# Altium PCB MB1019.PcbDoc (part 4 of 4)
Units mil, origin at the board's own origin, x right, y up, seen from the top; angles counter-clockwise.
Board outline 4655 x 6805 mil, 4 copper layers (TopLayer, VCC, GND, BottomLayer), stack 26.137 mil thick; 557 components, 425 nets, 1918 pads, 817 vias.
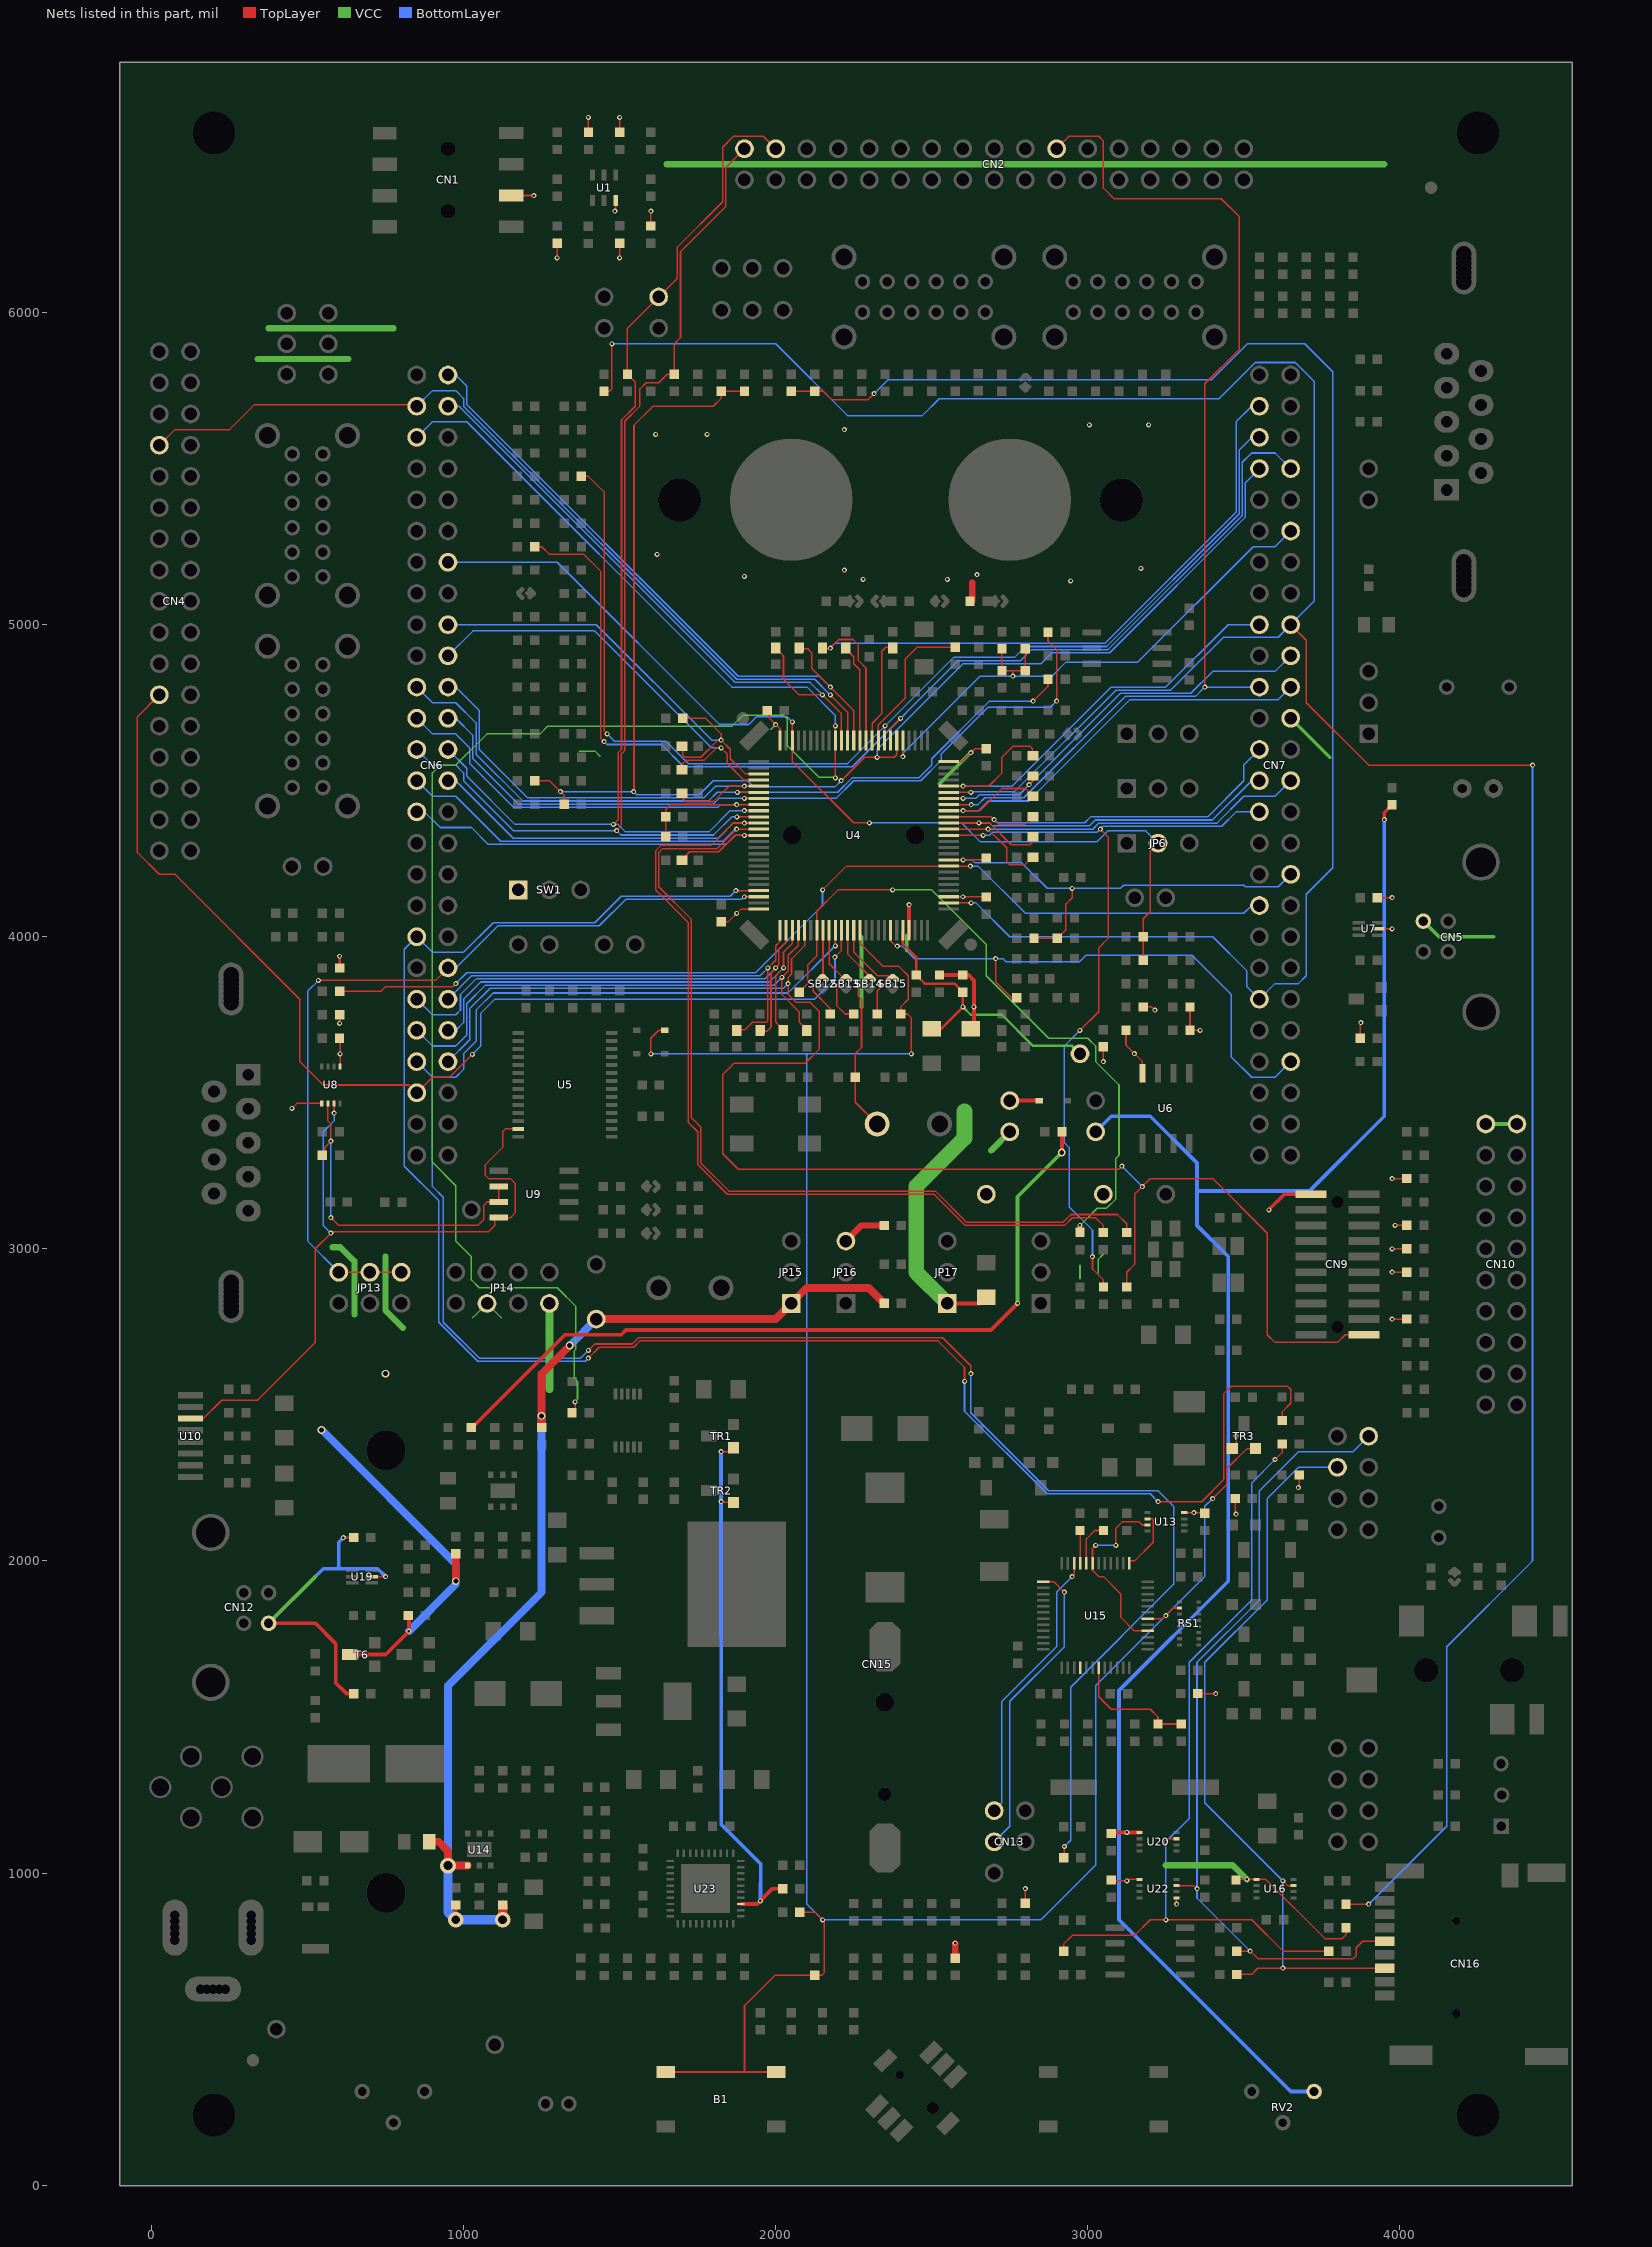
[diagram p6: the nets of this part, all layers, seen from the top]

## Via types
v1: diameter 16, hole 8, TopLayer to BottomLayer, tented both sides, 770 vias
v2: diameter 16, hole 8, TopLayer to BottomLayer, 26 vias
v3: diameter 25, hole 16, TopLayer to BottomLayer, tented both sides, 17 vias
v4: diameter 50, hole 28, TopLayer to BottomLayer, tented both sides, 4 vias

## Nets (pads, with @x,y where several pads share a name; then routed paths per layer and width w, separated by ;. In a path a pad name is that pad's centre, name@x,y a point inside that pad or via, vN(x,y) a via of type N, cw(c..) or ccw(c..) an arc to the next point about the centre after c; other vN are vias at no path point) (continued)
PC4: CN7.35 R177.2 U4.33 | length 3216.3
  TopLayer w5: R177.2@602.5,3825 735,3825 750,3840 965,3840 v1(975,3850) ; v1(2150,4150) 2226.58,4226.58 v1(2623.42,4226.58)
  BottomLayer w5: v1(975,3850) 1010,3885 1935,3885 2150,4100 v1(2150,4150) ; v1(2623.42,4226.58) 2648.42,4226.58 2800,4075 3500,4075 3525,4100 CN7.35@3550,4100
PC5: C33.2 CN7.34 R117.2 R118.2 U4.34 | length 1484.5
  TopLayer w5: U4.34@2554.13,4246.26 C33.2@2673.74,4246.26 ; R117.2@2827.5,3995 2902.5,3995 2930,4022.5 2930,4105 2950,4125 v1(2950,4155)
  BottomLayer w5: v1(2600.32,4246.26) 2628.74,4246.26 2638.42,4236.58 2788.42,4236.58 2870,4155 3105,4155 3115,4165 3500,4165 3505,4160 3610,4160 CN7.34@3650,4200
PC6: CN6.2 R47.2 R48.2 U4.63 | length 2056.3
  TopLayer w5: R47.2@2075,4922.5 2102.5,4922.5 2115,4910 2115,4860 2250,4725 U4.63@2250,4629.13
  BottomLayer w5: CN6.2@950,5800 975,5800 1010,5765 1010,5705 1880,4835 2140,4835 v1(2175,4800)
PC7: CN4.7 CN6.3 U4.64 | length 2796.8
  TopLayer w5: CN4.7@25,5575 75,5625 250,5625 330,5705 CN6.3@835,5705 ; v1(2175.14,4774.86) 2230.31,4719.69 U4.64@2230.31,4629.13
  BottomLayer w5: CN6.3@850,5700 900,5750 975,5750 1000,5725 1000,5700 1875,4825 2125,4825 v1(2175.14,4774.86)
PC8: CN6.4 R49.2 R50.2 U4.65 | length 2012.4
  TopLayer w5: R49.2@2000,4927.5 2000,4925 2025,4900 2025,4825 2075,4775 2149.73,4775 v1(2149.87,4775.13) ; v1@2150,4775 2210.63,4714.37 U4.65@2210.63,4629.13
  BottomLayer w5: CN6.4@950,5700 985,5700 1870,4815 2110,4815 v1(2149.87,4775.13)
PC9: CN6.5 R247.2 U4.66 | length 5848
  TopLayer w5: R247.2@1355,2475 1357.5,2477.5 v1(1357.5,2510) ; v1@2190.94,4510.94 v1(2190.94,4675.31)
  VCC w5: v1(1357.5,2510) 1365,2517.5 1365,2575 1355,2585 1355,2673.91 1360,2678.91 1360,2815 1300,2875 1050,2875 1025,2900 1025,2975 975,3025 975,3202.31 900,3277.31 900,4525 925,4550 975,4550 1075,4650 1245,4650 1270,4675 1860,4675 1895,4710 2025,4710 2036.85,4698.15 2036.85,4613.15 2139.06,4510.94 2190.94,4510.94 v1@2190,4510
  BottomLayer w5: CN6.5@850,5600 900,5650 1010,5650 1860,4800 2100,4800 2190.94,4709.06 v1(2190.94,4675.31)
  other v1: 1357.5,2510 2190.94,4509
PC10: CN6.18 R51.2 R52.2 R129.2 U4.78 | length 1550.6
  TopLayer w5: R51.2@1702.5,4610 1702.5,4582.5 1710,4575 1760,4575 1815,4630 v1(1825,4630) ; R129.2@1702.5,4700 1775,4700 1825,4650 v1(1825,4630) ; U4.78@1945.87,4521.85 1903.15,4521.85 1854.38,4570.62 1854.38,4600.62 v1(1825,4630)
  BottomLayer w5: CN6.18@950,5000 1425,5000 1795,4630 v1(1825,4630)
PC11: CN6.20 R53.2 R54.2 U4.79 | length 1407.7
  TopLayer w5: R53.2@1702.5,4535 1702.5,4555 1712.5,4565 1770,4565 1810,4605 v1(1825,4605) 1844.38,4585.62 1844.38,4555.62 1897.84,4502.17 U4.79@1945.87,4502.17
  BottomLayer w5: CN6.20@950,4900 1030,4980 1420,4980 1795,4605 v1(1825,4605)
PC12: CN6.22 R55.2 R56.2 U4.80 | length 1470.7
  TopLayer w5: R55.2@1702.5,4460 1702.5,4442.5 1711.57,4433.42 1800.94,4433.42 1850,4482.48 U4.80@1945.87,4482.48
  BottomLayer w5: CN6.22@950,4800 975,4800 1050,4725 1050,4600 1205,4445 1770,4445 1807.48,4482.48 v1(1900,4482.48)
PC13: R187.1 R308.2 U4.7 | length 2170.2
  TopLayer w5: R187.1@2075,3822.5 R187.1@2075,3825 ; R187.1@2075.16,3822.62 2103.26,3850.72 2103.26,3910 2131.89,3938.63 2131.89,4081.89 2200,4150 v1(2375,4150) ; R308.2@2975,3052.5 v1(2975,3075)
  VCC w5: v1(2375,4150) 2500,4150 2675,3975 2675,3875 2875,3675 3000,3675 3025,3650 3025,3600 3100,3525 3100,3300 3090,3290 3090,3160 3060,3130 3030,3130 v1(2975,3075)
PC14: R196.2 SB12.1 U4.8 | length 304.2
  TopLayer w5: U4.8@2151.57,4020.87 2151.57,3874.43 2120,3842.85 2120,3825 2175,3770 R196.2@2175,3752.5
PC15: R197.2 SB13.1 U4.9 | length 335.3
  TopLayer w5: U4.9@2171.26,4020.87 2171.26,3913.74 SB13.1@2217,3868 2195,3846 2195,3780 2222.5,3752.5 R197.2@2250,3752.5
PD0: CN6.21 R124.1 U4.81 | length 2487.4
  TopLayer w5: v1(1877.2,4462.8) U4.81@1945.87,4462.8 ; v1(2825,4755) 2872.5,4802.5 R124.1@2872.5,4825
  BottomLayer w5: CN6.21@850,4800 900,4750 975,4750 1040,4685 1040,4585 1190,4435 1785,4435 1812.8,4462.8 2198.65,4462.8 2245.86,4510 2460,4510 2500,4550 2500,4570 2685,4755 v1(2825,4755)
PD1: CN6.24 R105.2 U4.82 | length 2533.5
  TopLayer w5: v1(1900,4443.11) U4.82@1945.87,4443.11 ; R105.2@2872.5,4975 2872.5,4947.5 2900,4920 v1(2900,4755)
  BottomLayer w5: CN6.24@950,4700 975,4700 1030,4645 1030,4570 1175,4425 1800,4425 1818.11,4443.11 2193.11,4443.11 2250,4500 2465,4500 2530,4565 2530,4585 2680,4735 2880,4735 v1(2900,4755)
PD2: CN6.23 R153.1 R165.1 U4.83 | length 1573.3
  TopLayer w5: R165.1@1647.5,4315 1647.5,4407.5 1663.43,4423.42 U4.83@1945.87,4423.42
  BottomLayer w5: CN6.23@850,4700 900,4650 975,4650 1020,4605 1020,4555 1160,4415 1815,4415 1823.43,4423.42 v1(1875,4423.42)
PD3: C10.2 CN2.31 CN6.26 JP2.1 U4.84 | length 3684.7
  TopLayer w5: v1(1480,4360) 1495,4375 1495,4590 1506,4601 1506,5656 1550,5700 1550,5777.5 C10.2@1525,5802.5 1525,5950 1685,6110 1685,6210 1830,6355 1830,6530 1865,6565 1960,6565 CN2.31@2000,6525 ; v1(1900,4403.74) U4.84@1945.87,4403.74
  BottomLayer w5: CN6.26@950,4600 1010,4540 1010,4515 1165,4360 1495,4360 1519.06,4335.94 1785.94,4335.94 1853.74,4403.74 v1(1900,4403.74)
PD4: C12.2 CN2.33 CN6.25 U4.85 | length 3639.5
  TopLayer w5: v1(1490,4340) 1505,4355 1505,4585.86 1516,4596.86 1516,5651.86 1565,5700.86 1565,5755 1585,5775 1625,5775 1652.5,5802.5 C12.2@1675,5802.5 1675,5900 1695,5920 1695,6195 1840,6340 1840,6465 CN2.33@1900,6525 ; v1(1875.94,4384.06) U4.85@1945.87,4384.06
  BottomLayer w5: CN6.25@850,4600 900,4550 975,4550 1000,4525 1000,4500 1160,4340 v1(1490,4340) 1504.06,4325.94 1800.94,4325.94 1859.06,4384.06 v1(1875.94,4384.06)
PD5: CN6.28 R22.1 U4.86 | length 3899.1
  TopLayer w5: U4.86@1945.87,4364.37 1864.37,4364.37 1792.5,4292.5 1632.5,4292.5 1615,4275 1615,4150.71 1720,4045.71 1720,3405 1750,3375 1750,3270 1845,3175 2507.57,3175 2607.57,3075 2925,3075 2950,3100 3025,3100 3050,3075 R22.1@3050,3052.5
  BottomLayer w5: CN6.28@950,4500 975,4500 1159.06,4315.94 1815.94,4315.94 1864.37,4364.37 v1(1900,4364.37)
PD6: CN6.27 R12.1 U4.87 | length 4017.8
  TopLayer w5: U4.87@1945.87,4344.68 v1(1874.69,4344.68) 1812.5,4282.5 1637.5,4282.5 1625,4270 1625,4160 1730,4055 1730,3420 1760,3390 1760,3275 1850,3185 2511.72,3185 2611.72,3085 2920.86,3085 2945.86,3110 3095,3110 3125,3080 R12.1@3125,3052.5
  BottomLayer w5: CN6.27@850,4500 900,4450 975,4450 1119.06,4305.94 1830.94,4305.94 1869.69,4344.68 v1(1874.69,4344.68)
PD7: CN6.29 R57.2 R58.2 U4.88 | length 1379.6
  TopLayer w5: R57.2@1702.5,4250 1725,4272.5 1817.5,4272.5 1870,4325 U4.88@1945.87,4325
  BottomLayer w5: CN6.29@850,4400 875,4400 925,4350 1025,4350 1079.06,4295.94 1840.94,4295.94 1870,4325 v1(1900,4325)
PD8: C22.2 C23.2 CN7.12 R119.1 R123.1 U4.55 | length 1835.3
  TopLayer w5: v1(2407.48,4577.52) U4.55@2407.48,4629.13 ; R123.1@2722.5,4925 2725,4922.5 C22.2@2725,4852.5 C23.2@2800,4852.5 R119.1@2800,4922.5 ; v1(2760,4835) 2760,4852.5
  BottomLayer w5: v1(2407.48,4577.52) 2407.48,4587.48 2655,4835 2885,4835 2930,4880 3160,4880 3530,5250 3600,5250 CN7.12@3650,5300
PD9: C7.2 C26.2 CN7.7 R80.1 R146.1 U4.56 | length 4615.1
  TopLayer w5: R146.1@1227.5,4497.5 1227.5,4500 1275,4500 1322.5,4452.5 C26.2@1322.5,4425 ; v1@1546,4466 1546,5639.43 1606.57,5700 1800,5700 1825,5725 C7.2@1825,5747.5 R80.1@1900,5747.5 ; v1(2210,4500) 2285,4575 2380,4575 2387.79,4582.79 U4.56@2387.79,4629.13
  BottomLayer w5: v1(1310,4465) v1(1545,4465) 1555,4455 1755,4455 1800,4500 1910,4500 1930,4480 2190,4480 v1(2210,4500) ; v1(2325,4575) 2325,4600 2600,4875 2850,4875 2885,4910 3070,4910 3505,5345 3505,5455 CN7.7@3550,5500
PD10: CN7.8 R100.1 U4.57 | length 3648.6
  TopLayer w5: R100.1@1227.5,5250 1250,5250 1275,5225 1385,5225 1440,5170 1440,4635 v1(1450,4625) ; U4.57@2368.11,4629.13 2368.11,4668.11 v1(2400,4700)
  BottomLayer w5: v1(1450,4625) 1459.11,4615.89 1634.11,4615.89 1705,4545 2245,4545 2585,4885 2785,4885 2820,4920 3065,4920 3495,5350 3495,5520 3525,5550 3600,5550 CN7.8@3650,5500
PD11: CN7.5 R92.1 U4.58 | length 3601.6
  TopLayer w5: R92.1@1377.5,5475 1400,5475 1450,5425 1450,4660 v1(1460,4650) ; U4.58@2348.42,4629.13 2348.42,4673.42 v1(2350.29,4675.29)
  BottomLayer w5: v1(1460,4650) 1484.11,4625.89 1649.11,4625.89 1720,4555 2230,4555 2570,4895 2765,4895 2800,4930 3060,4930 3485,5355 3485,5560 3525,5600 CN7.5@3550,5600
PD12: R39.2 R40.2 U4.59 | length 472.1
  TopLayer w5: U4.59@2328.74,4629.13 2328.74,4678.74 2415,4765 2415,4890 2452.5,4927.5 R39.2@2575,4927.5
PD13: R41.2 R42.2 U4.60 | length 338.9
  TopLayer w5: U4.60@2309.05,4629.13 2309.05,4684.05 2340,4715 2340,4915 2352.5,4927.5 R41.2@2375,4927.5
PD14: CN7.3 R45.2 R46.2 U4.61 | length 2316.4
  TopLayer w5: R45.2@2150,4922.5 2172.5,4922.5 2202.38,4952.38 2247.62,4952.38 2265,4935 2265,4885 2289.37,4860.63 U4.61@2289.37,4629.13
  BottomLayer w5: v1(2175,4925) 2190,4940 3055,4940 3475,5360 3475,5650 3525,5700 CN7.3@3550,5700
PD15: R43.2 R44.2 U4.62 | length 311.9
  TopLayer w5: R43.2@2225,4922.5 2250,4897.5 2250,4875 2269.68,4855.32 U4.62@2269.68,4629.13
PE0: CN6.37 R250.1 U4.97 | length 6029.6
  TopLayer w5: v1(1400,2650) 1435,2685 1545,2685 1565,2705 2520,2705 2605,2620 v1(2605,2575) ; v1(1872.16,4147.83) U4.97@1945.87,4147.83 ; v1(3225,2190) 3365,2190 3435,2260 3435,2535 3460,2560 3640,2560 3650,2550 3650,2505 3622.5,2477.5 R250.1@3622.5,2450
  BottomLayer w5: v1(1400,2650) 1390,2640 1045,2640 920,2765 920,3155 810,3265 810,3960 CN6.37@850,4000 900,3950 1000,3950 1095,4045 1420,4045 1505,4130 1854.33,4130 v1(1872.16,4147.83) ; v1(2605,2575) 2605,2480 2870,2215 3200,2215 v1(3225,2190)
PE1: CN6.40 JP13.2 JP13.4 JP13.6 U4.98 | length 2715.5
  TopLayer w5: v1(535,3860) 910,3860 CN6.40@950,3900 ; JP13.2@600,2925 JP13.6@800,2925 ; v1(1899.69,4128.15) U4.98@1945.87,4128.15
  BottomLayer w5: v1(535,3860) 500,3825 500,3025 JP13.2@600,2925 ; CN6.40@950,3900 975,3900 1110,4035 1435,4035 1520,4120 1891.53,4120 v1(1899.69,4128.15) v1@1897.84,4130
PE2: CN6.42 R1.2 R2.2 U4.1 | length 1484.7
  TopLayer w5: R1.2@1875,3702.5 1902.5,3702.5 1926.5,3726.5 1971.5,3726.5 1975,3730 v1(1975,3900) 2000,3925 2000,3971.22 2013.78,3985 U4.1@2013.78,4020.87
  BottomLayer w5: CN6.42@950,3800 1025,3875 1950,3875 v1(1975,3900)
PE3: CN6.41 R3.2 R4.2 U4.2 | length 1633.3
  TopLayer w5: R3.2@1950,3697.5 1972.5,3697.5 1985,3710 1985,3885 2010,3910 2010,3960 2033.46,3983.46 U4.2@2033.46,4020.87
  BottomLayer w5: CN6.41@850,3800 900,3750 975,3750 990,3765 990,3815 1040,3865 1965,3865 v1(2000,3900)
PE4: CN6.44 R5.2 R6.2 U4.3 | length 1552.1
  TopLayer w5: R5.2@2024,3702.5 2000,3726.5 2000,3875 v1(2025,3900) 2025,3950 2053.15,3978.15 U4.3@2053.15,4020.87
  BottomLayer w5: CN6.44@950,3700 975,3700 1000,3725 1000,3800 1055,3855 1980,3855 v1(2025,3900)
PE5: CN6.43 R7.2 R8.2 U4.4 | length 1718.8
  TopLayer w5: U4.4@2072.83,4020.87 2072.83,3972.83 2040.58,3940.58 2040.58,3890.58 v1(2020,3870) 2020,3815 2075,3760 2075,3727.5 2100,3702.5 R7.2@2100,3697.5
  BottomLayer w5: CN6.43@850,3700 900,3650 975,3650 1010,3685 1010,3785 1070,3845 1995,3845 v1(2020,3870)
PE6: CN6.46 CN9.20 R111.2 U4.5 | length 5198.2
  TopLayer w5: U4.5@2092.52,4020.87 2092.52,3970.74 2050.58,3928.8 2050.58,3880 2040,3869.42 2040,3815 2065,3790 2110,3790 2140,3760 2140,3640 2095,3595 1866.57,3595 1830,3558.43 1830,3304.85 1879.85,3255 3099.39,3255 v1(3109.39,3265) ; R111.2@3125,2877.5 3125,2925 3150,2950 3150,3175 3200,3225 3400,3225 3575,3050 3575,2725 3600,2700 3800,2700 3825,2725 CN9.20@3885,2725
  BottomLayer w5: CN6.46@950,3600 1020,3670 1020,3770 1085,3835 2025,3835 v1(2040,3850) ; v1(3109.39,3265) v1(3174.69,3199.69)
PE7: CN7.29 R309.2 U4.38 | length 2614.6
  TopLayer w5: U4.38@2554.13,4325 v1(2665,4325) ; v1(2975,3700) 3035,3760 3035,3964.29 3065,3994.29 3065,4320 v1(3040,4345) ; v1(3015,2975) 3015,2935 3050,2900 R309.2@3050,2877.5
  BottomLayer w5: v1(2665,4325) 2685,4325 2694.68,4334.68 3029.68,4334.68 3049.06,4354.06 3429.06,4354.06 3475,4400 CN7.29@3550,4400 ; v1(2975,3700) 2925,3650 2925,3340 2940,3325 2940,3135 3015,3060 v1(3015,2975)
PE8: CN7.28 R23.2 R24.2 U4.39 | length 1387.5
  TopLayer w5: U4.39@2554.13,4344.68 v1(2680.32,4344.68) 2740,4285 2740,4240 2750,4230 2797.5,4230 R23.2@2822.5,4255
  BottomLayer w5: v1@2680.32,4343.83 v1(2680.32,4344.68) 3015.63,4344.68 3035,4364.06 3414.06,4364.06 3500,4450 3600,4450 CN7.28@3650,4500
PE9: CN7.27 R25.2 R26.2 U4.40 | length 1281.5
  TopLayer w5: U4.40@2554.13,4364.37 v1@2650.63,4364.37 ; v1(2650.63,4365) 2651.26,4364.37 2685.63,4364.37 2755,4295 2815,4295 2822.5,4302.5 R25.2@2822.5,4320
  BottomLayer w5: v1(2650.63,4365) 2685,4365 2695,4355 3005,4355 3024.06,4374.06 3399.06,4374.06 3525,4500 CN7.27@3550,4500
PE10: CN7.25 R27.2 R28.2 U4.41 | length 1269.5
  TopLayer w5: U4.41@2554.13,4384.06 2690.94,4384.06 2715,4360 2797.5,4360 R27.2@2822.5,4385
  BottomLayer w5: v1(2700,4375) 2710,4365 2990,4365 3009.06,4384.06 3384.06,4384.06 3500,4500 3500,4550 CN7.25@3550,4600
PE11: CN7.22 R29.2 R30.2 U4.42 | length 1527.1
  TopLayer w5: U4.42@2554.13,4403.74 2653.74,4403.74 2725,4475 2800,4475 2825,4450 R29.2@2827.5,4450
  BottomLayer w5: v1(2600.32,4403.74) 2650,4403.74 2681.26,4435 2810,4435 3135,4760 3610,4760 CN7.22@3650,4800
PE12: CN2.13 CN7.21 U4.43 | length 3501.6
  TopLayer w5: U4.43@2554.13,4423.42 v1(2626.58,4423.42) ; CN2.13@2900,6525 2940,6565 3035,6565 3050,6550 3050,6399.14 3084.14,6365 3427.57,6365 3485,6307.57 3485,5881.72 3375,5771.72 v1(3375,4800)
  BottomLayer w5: v1(2626.58,4423.42) 2648.42,4423.42 2670,4445 2795,4445 3120,4770 3345,4770 v1(3375,4800) CN7.21@3550,4800
PE13: CN7.20 R31.2 R32.2 U4.44 | length 1318.9
  TopLayer w5: U4.44@2554.13,4443.11 v1(2600.32,4443.11) ; v1(2812.12,4487.72) 2827.5,4503.1 R31.2@2827.5,4515
  BottomLayer w5: v1(2600.32,4443.11) 2640.94,4443.11 2652.83,4455 2780,4455 v1@2812.42,4487.42 ; v1(2812.12,4487.72) 2812.72,4487.72 3105,4780 3330,4780 3400,4850 3600,4850 CN7.20@3650,4900
PE14: CN7.18 R136.1 R140.2 U4.45 | length 9761.6
  TopLayer w5: R136.1@1450,5747.5 1467.5,5747.5 1475,5755 v2(1475,5900) ; U4.45@2554.13,4462.8 v1(2625.32,4462.8) ; CN7.18@3650,5000 3700,4950 3700,4750 3900,4550 v2(4425,4550) ; R140.2@3827.5,900 v2(3900,900)
  BottomLayer w5: v2(1475,5900) 2000,5900 2230,5670 2470,5670 2524,5724 3420.42,5724 3536.42,5840 3665,5840 3725,5780 3725,5075 3610,4960 3435,4960 3265,4790 3090,4790 2765,4465 2627.52,4465 v1(2625.32,4462.8) ; v2(3900,900) 4150,1150 4150,1725 4425,2000 v2(4425,4550)
PE15: CN7.17 R33.2 R34.2 U4.46 | length 1540.1
  TopLayer w5: U4.46@2554.13,4482.48 2682.48,4482.48 2725,4525 2725,4575 2760,4610 2815,4610 2822.5,4602.5 R33.2@2822.5,4580
  BottomLayer w5: v1(2600.32,4482.48) 2757.48,4482.48 3075,4800 3250,4800 3450,5000 CN7.17@3550,5000
PF0: C51.1 SB14.1 U4.12 X2.2 | length 695.3
  TopLayer w5: U4.12@2230.31,4020.87 2230.31,3944.69 SB14.1@2300,3875 ; SB14.1@2292,3868 2265,3841 2265,3810 2275,3800 2275,3645 2255,3625 2255,3470 X2.2@2325,3400
PF1: R205.1 SB15.1 U4.13 | length 354.1
  TopLayer w5: U4.13@2250,4020.87 2250,3951 2326,3875 2360,3875 SB15.1@2367,3868 2325,3826 R205.1@2325,3752.5
PF2: CN7.46 R11.1 U4.19 | length 1814.8
  TopLayer w5: U4.19@2368.11,4020.87 2368.11,3986.89 2385,3970 v1(2390,3970) ; v1(2705,3930) 2705,3855 2755,3805 R11.1@2772.5,3805
  BottomLayer w5: v1(2390,3970) 2405,3970 2445.68,3929.32 2704.32,3929.32 v1(2705,3930) ; v1@2705,3929.32 2728.25,3929.32 2737.57,3920 2973.28,3920 2993.28,3940 3335,3940 3460,3815 3460,3615 3525,3550 3600,3550 CN7.46@3650,3600
PF4: C8.2 CN7.41 R82.2 U4.27 | length 5162.4
  TopLayer w5: R82.2@2050,5747.5 2152.5,5747.5 2180,5720 2295,5720 v1(2315,5740) ; U4.27@2554.13,4108.47 v1(2626.53,4108.47)
  BottomLayer w5: v1(2315,5740) 2359,5784 3395.57,5784 3511.57,5900 3695,5900 3785,5810 3785,4220.86 3700,4135.86 3700,3875 3675,3850 3600,3850 CN7.41@3550,3800 3510,3840 3510,3890 3400,4000 2750,4000 2641.53,4108.47 v1(2626.53,4108.47)
PF6: CN6.14 JP6.2 R179.2 R180.2 U4.73 | length 3166.2
  TopLayer w5: v1(2053.15,4688.15) 2053.15,4561.85 2250,4365 v1(2300,4365) ; R179.2@3177.5,3925 3177.5,4057.5 3200,4080 3200,4275 JP6.2@3225,4300
  BottomLayer w5: CN6.14@950,5200 1300,5200 1820,4680 1913.43,4680 1938.43,4705 2036.3,4705 v1(2053.15,4688.15) ; v1(2300,4365) 2595,4365 2655,4305 3030,4305 3065,4340 3185,4340 JP6.2@3225,4300
PF9: CN6.45 R303.2 U4.10 | length 6467.6
  TopLayer w5: v1(1400,2675) 1420,2695 1540,2695 1560,2715 2535,2715 2625,2625 v1(2625,2600) ; v1(2190.94,3970.94) U4.10@2190.94,4020.87 ; R303.2@2925,1051.79 v2(2925,1085)
  BottomLayer w5: CN6.45@850,3600 900,3550 ; v1(1400,2675) 1375,2650 1050,2650 935,2765 935,3165 900,3200 900,3550 ; v1(2190.94,3970.94) 2039.78,3819.78 1094.78,3819.78 1040,3765 1040,3665 1000,3625 1000,3575 975,3550 900,3550 ; v1(2625,2600) 2625,2475 2875,2225 3225,2225 3275,2175 3275,1925 2945,1595 2945,1105 v2(2925,1085)
PF10: CN4.23 CN6.47 U4.11 | length 3582.2
  TopLayer w5: CN4.23@25,4775 -45,4705 -45,4270 25,4200 75,4200 475,3800 475,3600 550,3525 825,3525 CN6.47@850,3500 900,3550 955,3550 v1(1028.15,3623.15) ; v1(2190,3935) 2210.63,3955.63 U4.11@2210.63,4020.87
  BottomLayer w5: v1(1028.15,3623.15) 1055.4,3650.4 1055.4,3755.4 1100.32,3800.32 2125.32,3800.32 2190,3865 v1(2190,3935)
RESET#: B1.2 B1.3 C116.2 D1.1 R206.2 R304.2 RS1.3 TR3.1 U4.14 U15.18 | length 8039.2
  TopLayer w5: v1(1600,3625) 1600,3675 1625,3700 D1.1@1645,3700 ; B1.2@1647.84,362.5 B1.3@2002.16,362.5 ; 1895,362.5 1900,367.5 1905,362.5 ; 1900,362.5 1900,575 1997.5,672.5 2147.5,672.5 2155,680 2155,845 2125,875 R304.2@2077.5,875 ; U4.14@2270,4020.55 U4.14@2269.68,4020.87 2269.68,3980.32 2345,3905 2395,3905 2425,3875 2425,3800 2400,3775 2400,3752.5 2422.5,3752.5 2435,3740 v1(2435,3625) ; U15.18@3192.32,1815.16 3240.16,1815.16 3274.21,1849.21 RS1.3@3294,1849.21 ; v1(3400,2200) 3445,2245 3445,2295 3510,2360 TR3.1@3537.5,2360
  BottomLayer w5: v1(1600,3625) v1(2435,3625) ; 2095,3625 2100,3620 2105,3625 ; 2100,3625 2100,900 v1(2150,850) 2850,850 3025,1025 3025,1600 3375,1950 3375,2175 v1(3400,2200)
  other v1: 3250,1825
RS485_DIR_3V3: R217.2 U8.6 U9.2 U9.3 | length 1078.6
  TopLayer w5: R217.2@555,3300 555,3325 v1(575,3345) 575,3400 565.16,3409.84 U8.6@565.16,3465.94 ; v1(575,3100) 600,3075 1045,3075 1065,3095 1065,3140 1075,3150 U9.3@1112.5,3150 U9.2@1112.5,3200
  BottomLayer w5: v1(575,3100) v1(575,3345)
SPI2_MISO_3V3: R263.1 R311.1 R318.2 U20.7 | length 2664.6
  TopLayer w5: R318.2@2922.5,749 2922.5,772.5 2950,800 3150,800 3200,850 3525,850 3625.16,749.84 R311.1@3772.62,749.84 ; v1(3250,1100) 3259.84,1109.84 U20.7@3284.06,1109.84 ; v1(3600,2325) 3622.5,2347.5 R263.1@3622.5,2375
  BottomLayer w5: v2(3250,850) v1(3250,1100) 3325,1175 3325,1675 3525,1875 3525,2250 v1(3600,2325)
SPI2_MOSI_3V3: CN15.3 CN16.3 R319.2 U16.7 | length 2488.9
  TopLayer w5: R319.2@3477.5,675 3525,675 3544.69,694.69 3624.69,694.69 v2(3625,695) ; v2@3625,694.69 CN16.3@3960,694.69 ; v2(3625,975) 3640.16,959.84 U16.7@3659.06,959.84
  BottomLayer w5: v2(3625,695) v2(3625,975) 3375,1225 3375,1675 3575,1875 3575,2200 3675,2300 CN15.3@3800,2300
SPI2_SCK_3V3: CN15.2 CN16.5 R315.2 U22.7 | length 2643.3
  TopLayer w5: U22.7@3284.06,959.84 3340.16,959.84 v2(3350,950) ; R315.2@3477.62,749.84 v2@3520,749.84 ; v2(3520,750) 3545,725 3850,725 3860,735 3860,760.33 3880.97,781.3 CN16.5@3951.65,781.3
  BottomLayer w5: v2(3520,750) 3350,920 3350,1675 3550,1875 3550,2225 3675,2350 3850,2350 CN15.2@3900,2400
STL_USB_DM: R274.1 U15.32 | length 143.9
  TopLayer w5: U15.32@2995.47,1992.32 2995.47,2070.47 3022.5,2097.5 R274.1@3050,2097.5
STL_USB_DP: R273.1 U15.33 | length 105.5
  TopLayer w5: R273.1@2975,2097.5 2975.79,2096.71 U15.33@2975.79,1992.32
STM_JTCK_SWCLK: CN13.3 U15.37 | length 974.3
  TopLayer w5: U15.37@2857.68,1933.27 2891.73,1933.27 v1(2925,1900)
  BottomLayer w5: CN13.3@2700,1100 2750,1150 2750,1550 2925,1725 v1(2925,1900)
STM_JTMS_SWDIO: CN13.1 U15.34 | length 898.4
  TopLayer w5: v1(2950,1950) 2956.1,1956.1 U15.34@2956.1,1992.32
  BottomLayer w5: CN13.1@2700,1200 2725,1225 2725,1550 2900,1725 2900,1900 v1(2950,1950)
STM_RST: C92.2 R292.1 U15.7 | length 407.2
  TopLayer w5: U15.7@3034.84,1657.68 3034.84,1565.16 3075,1525 3200,1525 3225,1500 C92.2@3225,1477.5 R292.1@3300,1477.5
SWIM_PU_CTRL: U15.4
T_SWDIO_IN: U13.2 U15.25 | length 190.9
  TopLayer w5: U15.25@3135,2000 3150,2000 3210,2060 3210,2130 3205.16,2134.84 U13.2@3190.94,2134.84
T_SWO: U13.3 U15.16 U15.31 | length 619
  TopLayer w5: v1(3025,2050) 3015.16,2040.16 3015.16,1969.84 3035,1950 3050,1950 3105,1895 3105,1820 3149.21,1775.79 U15.16@3192.32,1775.79 ; v1(3090,2050) 3090,2105 3110,2125 3165,2125 3174.84,2115.16 U13.3@3190.94,2115.16
  BottomLayer w5: v1(3025,2050) v1(3090,2050)
TS_SHIELD: R103.2 | length 60
  TopLayer w20: R103.2@2630,5075 2630,5135
  other v1: 2945,5140 2280,5145 2550,5145 1900,5155 2645,5160 2220,5175 3170,5180 1620,5225 1615,5610 1780,5610 2220,5625 3005,5640 3195,5640
U5V: C63.1 CN12.1 JP14.3 R283.1 U19.5 | length 1446.9
  TopLayer w5: v1(615,2075) C63.1@647.5,2075 ; U19.5@706.3,1950 v1(750,1950)
  TopLayer w12: CN12.1@375,1800 525,1800 590,1735 590,1610 625,1575 R283.1@647.5,1575
  VCC w5: 1030,2780 JP14.3@1075,2825 1120,2780
  VCC w12: CN12.1@375,1800 525,1950
  BottomLayer w5: 590,1975 600,1985 610,1975
  BottomLayer w12: CN12.1@375,1800 550,1975 725,1975 v1(750,1950) ; 600,1975 600,2060 v1(615,2075)
U5V_ST_LINK: C30.1 CN5.1 JP14.7 R213.1 U7.5 | length 662.9
  TopLayer w5: R213.1@3872.5,3675 3872.5,3722.5 v1(3875,3725) ; C30.1@3927.5,4125 v1(3975,4125) ; U7.5@3931.3,4025 v1(3975,4025)
  VCC w12: CN5.1@4075,4050 4125,4000 4300,4000
  VCC w25: 1275,2550 JP14.7@1275,2825
USART1_TXD_3V3: U5.13 U8.7 U9.4 U10.3 | length 2361.3
  TopLayer w5: U10.3@125,2456.1 166.1,2456.1 225,2515 340,2515 525,2700 525,3000.24 v1(574.88,3050.12) ; v1@575,3050 580,3055 1080,3055 1100,3075 1100,3100 1150,3100 1165,3115 1165,3210 1150,3225 1080,3225 1070,3235 1070,3270 1125,3325 1125,3375 1134.25,3384.25 U5.13@1175.39,3384.25 ; v1(584.84,3435.16) U8.7@584.84,3465.94
  BottomLayer w5: v1(574.88,3050.12) 550,3075 550,3375 584.84,3409.84 v1(584.84,3435.16)
VDD: C1.2 C40.2 C49.2 C72.1 C107.1 C109.2 C113.2 C130.2 CN1.5 CN7.24 CN9.1 CN10.1 CN10.2 JP12.2 JP16.3 R60.2 R61.2 R65.2 R71.1 R139.2 R186.2 R189.2 R199.2 R200.2 R201.1 R212.1 R218.2 R227.1 R229.2 R232.2 R233.2 R235.2 R253.1 R264.1 R271.2 R276.2 R288.1 R312.2 R326.1 SW1.1 T6.3 TP3.1 TR1.2 TR2.2 TR3.2 U1.3 U6.8 U8.1 U8.5 U13.8 U16.1 U20.1 U22.1 U22.5 U23.33 | length 9801
  TopLayer w5: v1(450,3450) 465.94,3465.94 U8.5@545.47,3465.94 ; C40.2@602.5,3675 604.53,3672.97 U8.1@604.53,3584.06 ; v1(602.5,3722.5) R189.2@602.5,3750 ; CN1.5@1152.5,6375 v1(1225,6375) ; v1(1300,6175) R65.2@1300,6222.5 ; R60.2@1399,6576.5 v1@1399,6624 ; v1(1485,6325) 1487.4,6327.4 U1.3@1487.4,6358.66 ; v1(1500,6175) R71.1@1500,6222.5 ; R61.2@1500,6577.5 v1(1500,6625) ; C1.2@1600,6277.5 v1(1600,6325) ; v1(1825,2190) 1827.5,2187.5 TR2.2@1865,2187.5 ; v1(1825,2350) TR1.2@1865,2350 ; R312.2@2800,902.5 v1(2800,950) ; v1(3050,3600) C49.2@3050,3647.5 ; C113.2@3077.5,975 v1(3125,975) 3129.53,979.53 U22.1@3165.94,979.53 ; R212.1@3122.5,3700 3122.5,3652.5 3175,3600 U6.8@3175,3562.5 ; R199.2@3177.5,3775 3205,3775 v1(3215,3765) ; v1@3284.06,900.94 U22.5@3284.06,920.47 ; U13.8@3309.06,2154.53 C72.1@3372.97,2154.53 ; R201.1@3327.5,3692.5 R200.2@3327.5,3775 ; R201.1@3327.5,3700 v1(3360,3700) ; R288.1@3352.5,1575 v1(3410,1575) ; R271.2@3472.5,2200 3472.5,2152.5 v1(3475,2150) ; TR3.2@3475,2362.5 v1(3475,2400) ; C130.2@3477.03,979.53 3570.47,979.53 3760,790 3815,790 3827.5,802.5 R139.2@3827.5,825 ; v1(3675,2235) 3677.5,2237.5 R264.1@3677.5,2275 ; v1(3975,2775) R235.2@4022.5,2775 ; v1(3975,2925) R232.2@4022.5,2925 ; v1(3975,3000) R233.2@4022.5,3000 ; v1(3975,3225) R218.2@4022.5,3225 ; v1(3985,3075) R229.2@4022.5,3075
  TopLayer w8: R186.2@602.5,3900 v1(602.5,3937.5)
  TopLayer w12: T6.3@635,1700.5 750.5,1700.5 v1(825,1775) 825,1822.5 R276.2@822.5,1825 ; U23.33@1887.99,900.79 1940.79,900.79 1990,950 C107.1@2022.5,950 ; C109.2@3078.03,1129.53 U20.1@3165.94,1129.53 ; v1(3580,3125) 3630,3175 CN9.1@3715,3175
  TopLayer w20: JP16.3@2225,3025 2275,3075 R227.1@2347.5,3075 ; R326.1@2575,727.5 v1(2575,775)
  TopLayer w25: v3(975,1935) R253.1@975,2022.5
  VCC w5: 1370,4595 1420.63,4595 1437.71,4577.91 ; 2975,2903.75 2975,2946.54 ; 3032.85,2921.81 3032.85,2966.18 3049.67,2983
  VCC w12: CN7.24@3650,4700 3775,4575 ; CN10.1@4265,3400 CN10.2@4375,3400
  VCC w20: 340.79,5850.79 630.79,5850.79 ; 375,5950 775,5950 ; 580,3005 605,3005 650,2960 650,2790 ; 750,2975 750,2802.09 805,2747.09 ; 1650,6475 3950,6475 ; 2690,3315 JP12.2@2750,3375 ; 3250,1025 3464.53,1025 v2(3510,979.53)
  BottomLayer w12: v1(1825,2350) 1825.72,1155.44 1951.83,1029.33 v1(1951.11,911.11)
  BottomLayer w25: v3(545,2420) 975,1990 975,1925 v1(825,1775)
  other v1: 3285,900 3125,1130 3340,2154.53 604.53,3625 3149.43,3625.57 1400,6625
  other v3: 750,2600
VDD_ADJ: C75.1 C77.2 JP15.1 R231.2 R246.2 R286.1 TP7.1 U14.4 | length 3580.4
  TopLayer w12: v4(975,850) C77.2@975,897.5
  TopLayer w25: C75.1@890,1100 919.98,1100 950,1069.98 v4(950,1023.82) 975,1023.82 U14.4@1012.6,1023.82 ; R246.2@1250,2427.5 1250,2600 v3(1340,2690) ; TP7.1@1425,2775 2000,2775 2100,2875 2297.5,2875 R231.2@2347.5,2825
  TopLayer w30: v4(1125,850) R286.1@1125,897.5
  BottomLayer w25: v4(950,1023.82) 950,1600 1250,1900 v3(1250,2465) ; v3(1340,2690) TP7.1@1425,2775
  BottomLayer w30: v4(950,1023.82) 950,875 v4(975,850) v4(1125,850)
VDD_ANA: JP11.1 R158.2 RV2.1 | length 5607.6
  TopLayer w12: v1(3950,4375) 3950,4397.5 R158.2@3975,4422.5
  BottomLayer w5: 3350,3175 3360,3185 3350,3195
  BottomLayer w12: JP11.1@3025,3375 3075,3425 3200,3425 3350,3275 3350,3075 3450,2975 3450,1935 3100,1585 3100,850 3650,300 RV2.1@3725,300 ; 3350,3185 3710,3185 3950,3425 v1(3950,4375)
VDDA: C39.2 C48.1 L1.2 R188.1 R254.1 TP2.1 U4.22 | length 2946.1
  TopLayer w12: R254.1@1025,2427.5 1027.5,2427.5 1325,2725 1505,2725 1520,2740 2690,2740 v1(2775,2825) ; U4.22@2427.16,4000 v1(2427.16,4102.84) ; C39.2@2525,3877.5 2617.5,3877.5 2635,3860 C48.1@2635,3705 ; v3@2917.5,3309.42 L1.2@2917.5,3375
  VCC w12: 2420,3956.25 2420,4005 ; v1(2775,2825) 2775,3166.92 v3(2916.54,3308.46)
  other v1: 2635,3775
VDDIO: C20.1 C25.1 C31.2 C32.1 C117.1 D3.1 JP12.1 JP17.1 U4.28 U4.50 U4.75 U4.100 | length 1878.5
  TopLayer w5: C31.2@1825,4047.5 1847.5,4047.5 1888.78,4088.78 U4.100@1945.87,4088.78 ; C20.1@1980,4725 1980,4700 2013.78,4666.22 U4.75@2013.78,4629.13 ; U4.28@2554.13,4128.15 C32.1@2674.35,4128.15 ; U4.50@2554.13,4561.22 2596.22,4561.22 2637.5,4602.5 C25.1@2675,4602.5
  TopLayer w12: JP17.1@2550,2825 2655,2825 C117.1@2675,2845 ; JP12.1@2750,3475 D3.1@2845,3475
  VCC w5: 1985,4665 v1(2000,4680) ; 2600,4565 v1(2625.21,4590.21)
  VCC w12: 2275,3775 2275,4000 ; 2525,4490 v1(2625.21,4590.21)
  VCC w50: JP17.1@2550,2825 2450,2925 2450,3200 2605,3355 2605,3440
  other v1: 1875.12,4075.12 2600,4128.15
VREF+: C38.2 C47.1 R188.2 TP1.1 U4.21 | length 947.4
  TopLayer w8: U4.21@2407.48,4020.87 2407.48,3977.52 2450,3935 C38.2@2450,3877.5 2477.5,3850 2572.5,3850 2600,3822.5 v1(2600,3775) 2530,3705 C47.1@2500,3705
  VCC w8: v1(2600,3775) 2625,3750 2725,3750 2825,3650 2950,3650 TP1.1@2975,3625
pads on no net: BT1.0 CN1.0 CN1.2 CN1.6 CN1.8 CN3.1 CN3.4 CN3.8 CN7.52 CN8.1 CN8.7 CN9.0 CN9.7 CN11.5 CN11.7 CN11.G1 CN11.G2 CN13.5 CN15.0 CN15.4 CN15.5 CN15.6 CN16.1 CN16.8 CN16.g D6.1 D7.1 D8.1 D9.1 D10.1 D11.1 MP1.0 MP2.0 MP3.0 MP4.0 OAM1.10 OAM1.11 OAM1.12 OAM2.10 OAM2.11 OAM2.12 PGM1.10 PGM1.11 PGM1.12 PGM2.10 PGM2.11 PGM2.12 RS1.1 RS1.2 RS1.15 RS1.16 U3.5 U4.0 U5.7 U5.8 U5.9 U5.11 U5.12 U5.14 U5.15 U5.16 U5.18 U5.21 U6.1 U10.2 U12.4 U14.3 U15.11 U15.12 U15.13 U15.14 U15.21 U15.22 U15.28 U15.38 U15.39 U15.40 U15.41 U15.42 U15.43 U15.45 U15.46 U20.3 U22.6 U23.4 U23.6 U23.7 U23.9 U23.22 U23.24 U23.25 U23.26 U23.29 U23.30 U27.G X1.2 X1.3
copper on no net: | length 6395
  TopLayer w5: 2475,1275 2575,1275 ; 2475,1325 2575,1325 ; 2475,1375 2575,1375 ; 2475,1425 2575,1425 ; 2475,1475 2575,1475 ; 2525,1225 2525,1525 ; 2475,1225 2475,1230 2475,1525 2575,1525 2575,1225 2475,1225
  GND w5: 2475,1275 2575,1275 ; 2475,1325 2575,1325 ; 2475,1375 2570,1375 ; 2475,1425 2575,1425 ; 2475,1475 2575,1475 ; 2525,1225 2525,1525 ; 2475,1225 2475,1525 2575,1525 2575,1225 2475,1225
  VCC w5: 2475,1275 2575,1275 ; 2475,1325 2575,1325 ; 2475,1375 2570,1375 2575,1375 ; 2475,1425 2575,1425 ; 2475,1475 2575,1475 ; 2525,1225 2525,1525 ; 2475,1225 2475,1525 2575,1525 2575,1225 2475,1225
  BottomLayer w5: 2475,1275 2575,1275 ; 2475,1325 2575,1325 ; 2475,1375 2575,1375 ; 2475,1425 2575,1425 ; 2475,1475 2575,1475 ; 2525,1225 2525,1525 ; 2475,1225 2475,1525 2575,1525 2575,1225 2475,1225

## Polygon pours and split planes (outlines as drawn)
NetC79_2 on TopLayer "TopLayer-NetC79_2" (hatched 90Degree grid 20 track 10, remove dead copper, pour order 6): -100,2175 305,2175 385,2095 385,2020 285,1920 285,1775 365,1695 580,1695 590,1685 590,1555 570,1535 560,1525 -100,1525
TS_SHIELD on TopLayer "TopLayer-TS_SHIELD" (hatched 90Degree grid 10 track 10, remove dead copper, pour order 4): 2660,5050 2705,5050 2705,5125 3205,5125 3205,5675 1595,5675 1595,5125 2630,5125 2645,5110 2645,5055 2650,5050
GND on TopLayer "TopLayer-GND" (hatched 90Degree grid 20 track 10, remove dead copper, pour order 2): 675,6800 4550,6800 4550,0 -100,0 -100,6100 650,6100 675,6125
GND on GND "GND-GND" (hatched 90Degree grid 5 track 5, remove dead copper, pour order 8): 665,6800 4550,6800 4550,0 -100,0 -100,6095 670,6095 670,6800
TS_SHIELD on VCC "VCC-TS_SHIELD" (hatched 90Degree grid 10 track 10, remove dead copper, pour order 34): 1580,5690 3225,5690 3225,5120 2720,5120 2720,4895 2490,4665 2245,4665 2245,4725 2185,4785 2185,5035 2120,5100 1580,5100
D5V on VCC "VCC-D5V" (hatched 90Degree grid 10 track 10, remove dead copper, pour order 32): 825,2750 1025,2750 1025,2947.91 950,3022.91 950,3155 907.57,3197.43 880,3225 880,4620 930,4670 1580,4670 1630,4720 2025,4720 2053.15,4691.85 2053.15,4620 2123.15,4550 2173.15,4500 2500,4500 2650,4650 3600,4650 3600,4975 3497.87,4975 3402.87,4880 2710,4880 2480,4650 2225,4650 2225,4725 2060,4890 750,4890 570,4710 570,4150 665,4055 665,3160 835,2990 835,2800 820,2785 820,2750
+3V3 on VCC "VCC-+3V3" (hatched 90Degree grid 10 track 10, remove dead copper, pour order 30): 418.38,4270 600,4270 600,4700 830,4930 995,4930 1025,4900 2945,4900 2970,4875 3400,4875 3525,5000 3525,5720 3550,5745 3875,5745 3910,5780 3910,6335 3815,6430 1865,6430 1675,6240 1675,6115 1655,6095 1055,6095 770,5810 405,5810 375,5780 375,4330 419.34,4285.66 419.34,4270.66
+5V on VCC "VCC-+5V" (hatched 90Degree grid 10 track 10, remove dead copper, pour order 28): -100,2650 620,2650 620,2800 200,2800 25,2975 25,5875 175,6025 750,6025 800,6075 800,6625 850,6675 2225,6675 2250,6650 2250,6475 2355,6475 2355,6800 675,6800 675,6125 650,6100 -100,6100
VDDIO on VCC "VCC-VDDIO" (hatched 90Degree grid 10 track 10, remove dead copper, pour order 26): 1905,4700 2025,4700 2035,4690 2035,4620 2165,4490 2490,4490 2623.15,4623.15 2650,4623.15 2650,4100 2575,4100 2525,4150 2350,4150 2350,3850 2650,3550 2675,3525 2775,3525 2775,3425 2150,3425 2150,3905 2105,3950 1850,3950 1850,4675 1875,4700
VDDA on VCC "VCC-VDDA" (hatched 90Degree grid 10 track 10, remove dead copper, pour order 24): 2365,4135 2520,4135 2600,4055 2650,4005 2650,3775 2800,3625 3080,3625 3080,3150 2775,3150 2775,3525 2730,3570 2665,3570 2345,3890 2345,4130 2370,4130
U5V on VCC "VCC-U5V" (hatched 90Degree grid 10 track 10, remove dead copper, pour order 22): 1005,2875 1125,2875 1125,2700 925,2500 925,2275 400,1750 -100,1750 -100,2175 305,2175 380,2100 525,2100 525,2275 1000,2750 1000,2875
E5V on VCC "VCC-E5V" (hatched 90Degree grid 10 track 10, remove dead copper, pour order 20): -100,1125 500,1125 500,1625 1225,2350 1225,2875 1125,2875 1125,2700 925,2500 925,2270 400,1745 -100,1745
U5V_ST_LINK on VCC "VCC-U5V_ST_LINK" (hatched 90Degree grid 10 track 10, remove dead copper, pour order 18): 1225,2850 1350,2850 1350,2355 675,1680 675,350 750,275 850,175 3999.34,175 4350.8,526.46 4399.34,575 4399.34,3575 3825,3575 3825,4175 4550,4175 4550,0 -100,0 -100,1105 515,1105 515,1620 1235,2340 1235,2850
+2V5 on VCC "VCC-+2V5" (hatched 90Degree grid 10 track 10, remove dead copper, pour order 16): 1375,1600 2050,1600 2050,1000 2025,1000 1850,825 1550,825 1550,1050 1850,1050 1875,1075 1875,1275 1675,1475 1375,1475
+5V on VCC "VCC-+5V 1" (hatched 90Degree grid 10 track 10, remove dead copper, pour order 14): 985,3050 1480,3050 1650,2880 1650,2425 1175,1950 1175,1725 1300,1725 1300,1825 1325,1850 1525,1850 1675,1700 2125,1700 2775,2350 2775,2530 2875,2530 2875,2350 2150,1625 1375,1625 1375,1470 1670,1470 1875,1265 1875,1090 1835,1050 1540,1050 1540,825 675,825 675,1680 1350,2355 1350,2827.16 990,2827.16 977.16,2840 977.16,3050
+3V3 on VCC "VCC-+3V3 1" (hatched 90Degree grid 10 track 10, remove dead copper, pour order 12): 950,4000 1550,4000 1650,3900 1650,3600 2100,3150 2100,2675 2125,2650 3100,2650 3125,2675 3125,3100 3250,3225 3300,3225 3300,3155 3225,3080 3225,2600 3250,2575 3600,2575 3600,2500 3250,2500 3225,2475 3225,2190 3275,2140 3275,1675 3425,1525 3725,1525 3800,1600 3800,2100 4150,2100 4150,650 3425,650 3350,725 3325,750 3325,1129.53 3279.53,1175 3050,1175 3000,1125 3000,600 2875,600 2875,950 2850,975 2525,975 2350,800 2350,425 1925,425 1925,500 2225,500 2225,950 2055,950 2055,1595 2070,1610 2155,1610 2885,2340 2885,2540 2765,2540 2765,2360 2120,1715 1680,1715 1530,1865 1300,1865 1300,1730 1175,1730 1175,1970 1650,2445 1650,2925 1515,3060 950,3060 950,3155 890,3215 890,4000
VDD on VCC "VCC-VDD" (hatched 90Degree grid 10 track 10, remove dead copper, pour order 10): -98,2201 303,2201 388,2116 510,2116 510,2285 897,2672 897,2729 826,2729 826,2995 665,3156 622,3199 622,4083 474,4231 325,4231 325,5747 383,5805 760,5805 1050,6095 1660,6095 1660,6245 1842,6427 3815,6427 3910,6332 3910,5769 3886,5745 3681,5745 3636,5700 3598,5662 3598,4640 2695,4640 2645,4590 2645,3770 2700,3770 2720,3750 2820,3650 2980,3650 3100,3530 3100,3175 3065,3140 2775,3140 2775,3437.25 2725,3437.25 2705,3417.25 2660,3372.25 2206.02,3372.25 2153.27,3425 2153.27,3885 2113.27,3925 1845,3925 1845,4700 993.13,4700 993.13,4050 1740,4050 1740,3570 2120,3190 2120,2700 2145,2675 3090,2675 3110,2695 3110,3105 3205,3200 3285,3200 3285,3125 3235,3075 3235,2610 3255,2590 3610,2590 3610,2490 3260,2490 3235,2465 3235,2205 3285,2155 3285,1685 3430,1540 3710,1540 3780,1610 3780,2070 4160,2070 4160,640 3425,640 3320,745 3320,1129.53 3284.53,1165 3055,1165 3010,1120 3010,590 2865,590 2865,950 2840,975 2525,975 2360,810 2360,420 1915,420 1915,505 2210,505 2210,925 1950,925 1840,815 695,815 695,345 845,195 3995,195 4385,585 4385,3555 3820,3555 3820,4195 4545,4195 4545,6805 2365,6805 2365,6520 2245,6520 2245,6645 880,6645 845,6610 830,6595 830,6075 770,6015 185,6015 35,5865 35,3005 190,2850 560,2850 640,2770 640,2635 -100,2635 -100,2200
GND on BottomLayer "BottomLayer-GND" (hatched 90Degree grid 20 track 10, remove dead copper, pour order 38): 675,6800 4550,6800 4550,0 -100,0 -100,6100 650,6100 675,6125
no net on BottomLayer "BottomLayer-No Net" (hatched 90Degree grid 10 track 10, remove dead copper, pour order 36): 2800,4500 2800,4475 2825,4475

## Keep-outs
KeepOutLayer:
  lines w5: 4550,476.01 cw(c5723.78,725.51) 4550,975 4550,6800 1505.64,6800 -100,6800 -100,1950 -100,0 4550,0 4550,476.01 ; 4550,476.01 4550,476.01

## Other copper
TopLayer:
  text "1" at 2520,1290 h35 r90
  text "B" at 2570,1285 h35 r90
GND:
  text "4" at 2520,1465 h35 r90
  text "B" at 2567,1440 h35 r90
VCC:
  text "2" at 2515,1335 h35 r90
  text "B" at 2570,1335 h35 r90
BottomLayer:
  text "3" at 2520,1410 h35 r90
  text "B" at 2570,1385 h35 r90

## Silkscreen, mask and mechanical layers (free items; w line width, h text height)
TopOverlay:
  drawing of 10014 lines, arcs and shapes, not listed
  text "1" at 1195,6680 h40
  text "MB1019 rev.C" at 645,5975 h60
  text "SMB" at 1385,5900 h35 r90
  text "MC1_EnA" at 1565,5900 h35 r90
  text "1" at 825,5865 h40
  text "2" at 925,5865 h40
  text "1" at 3540,5865 h40
  text "2" at 3640,5865 h40
  text "GND" at 3350,5785 h40
  text "GND" at 675,5775 h40
  text "PC6" at 1035,5750 h40 r45
  text "PD15" at 3735,5750 h40 r45
  text "PC7" at 675,5675 h40
  text "PD14" at 3350,5675 h40
  text "PC8" at 1035,5650 h40 r45
  text "PD13" at 3735,5650 h40 r45
  text "PC9" at 680,5575 h40
  text "PD11" at 3350,5575 h40
  text "PA8" at 1035,5550 h40 r45
  text "PD12" at 3735,5550 h40 r45
  text "PA10" at 650,5475 h40
  text "PD9" at 3350,5475 h40
  text "PA9" at 1035,5450 h40 r45
  text "PD10" at 3735,5450 h40 r45
  text "PA11" at 650,5375 h40
  text "PC13" at 3350,5375 h40
  text "GND" at 3730,5375 h40
  text "GND" at 1035,5350 h40 r45
  text "CAN terminal" at 4010,5305 h35 r90
  text "PC14" at 650,5275 h40
  text "RST" at 3350,5275 h40
  text "PD8" at 3720,5275 h40
  text "PA12" at 1035,5250 h40 r45
  text "PA13" at 650,5175 h40
  text "PB15" at 3350,5175 h40
  text "PB14" at 3720,5175 h40
  text "PF6" at 1035,5150 h40 r45
  text "PB10" at 3720,5075 h40
  text "PC15" at 700,5050 h40 r45
  text "PA14" at 1035,5050 h40 r45
  text "PB13" at 3400,5050 h40 r45
  text "PE14" at 3720,4975 h40
  text "PC10" at 1030,4960 h40 r45
  text "PA15" at 700,4950 h40 r45
  text "PE15" at 3400,4950 h40 r45
  text "GND" at 700,4850 h40 r45
  text "PC11" at 1035,4850 h40 r45
  text "D5V" at 3400,4850 h40 r45
  text "PE13" at 3750,4850 h40 r45
  text "REF" at 4015,4825 h35 r90
  text "PD0" at 675,4775 h40
  text "PE11" at 3725,4775 h40
  text "PC12" at 1035,4750 h40 r45
  text "PE12" at 3400,4750 h40 r45
  text "CAN_RS" at 3175,4715 h35
  text "PD2" at 675,4675 h40
  text "VDD" at 3725,4675 h40
  text "PD1" at 1035,4650 h40 r45
  text "PF0" at 3410,4650 h40 r45
  text "HUM" at 4015,4600 h35 r90
  text "PD4" at 675,4575 h40
  text "PF1" at 3730,4575 h40
  text "PE10" at 3410,4555 h40 r45
  text "PD3" at 1035,4550 h40 r45
  text "I2C2" at 3075,4540 h35
  text "I2C_F" at 3250,4540 h35
  text "PD6" at 675,4475 h40
  text "PE8" at 3730,4475 h40
  text "PD5" at 1035,4450 h40 r45
  text "PE9" at 3420,4450 h40 r45
  text "GND" at 3730,4375 h40
  text "I2C2" at 3075,4360 h35
  text "I2C_F" at 3250,4360 h35
  text "BOOT0" at 1280,4355 h35
  text "PD7" at 725,4350 h40 r45
  text "PE7" at 3420,4350 h40 r45
  text "GND" at 1035,4345 h40 r45
  text "0 = Flash" at 1150,4305 h35
  text "MC2_EnA" at 385,4290 h35
  text "PB4" at 675,4275 h40
  text "PB3" at 1025,4275 h40
  text "PB1" at 3720,4275 h40
  text "1 = Sys mem" at 1155,4260 h35
  text "PB2" at 3420,4250 h40 r45
  text "0<-->1" at 1175,4215 h35
  text "E2P_WC" at 3120,4195 h35
  text "PB6" at 675,4175 h40
  text "PB5" at 1035,4175 h40 r45
  text "PC5" at 3720,4175 h40
  text "PB0" at 3425,4150 h40 r45
  text "PB8" at 675,4075 h40
  text "PA7" at 3720,4075 h40
  text "PB7" at 1035,4070 h40 r45
  text "PC4" at 3425,4050 h40 r45
  text "BL_Boot0" at 1120,4040 h35
  text "BL_RST" at 1400,4040 h35
  text "PE0" at 675,3975 h40
  text "PB9" at 1015,3975 h40
  text "PA5" at 3720,3975 h40
  text "PA6" at 3425,3950 h40 r45
  text "GND" at 675,3875 h40
  text "PE1" at 1025,3875 h40
  text "PA4" at 3730,3875 h40
  text "GND" at 3420,3850 h40 r45
  text "PE3" at 685,3775 h40
  text "PE2" at 1025,3775 h40
  text "PA3" at 3720,3775 h40
  text "1" at 1725,3770 h40
  text "PF4" at 3425,3750 h40 r45
  text "PE5" at 685,3675 h40
  text "PE4" at 1025,3675 h40
  text "VREF+" at 2875,3675 h35
  text "PA2" at 3375,3675 h40
  text "PA1" at 3720,3675 h40
  text "PF9" at 685,3575 h40
  text "PE6" at 1025,3575 h40
  text "PA0" at 3375,3575 h40
  text "PF2" at 3720,3575 h40
  text "PF10" at 660,3475 h40
  text "3V3" at 1030,3475 h40
  text "PC3" at 3375,3475 h40
  text "PC2" at 3720,3475 h40
  text "PC1" at 3375,3400 h40
  text "D5V" at 675,3375 h40
  text "GND" at 1030,3375 h40
  text "GND" at 3735,3375 h40
  text "VDDIO" at 2690,3325 h40 r90
  text "VDD_ANA" at 3125,3300 h40 r90
  text "PC0" at 3375,3275 h40
  text "PB11" at 675,3270 h40
  text "PB12" at 1035,3235 h40 r45
  text "51" at 825,3200 h40
  text "52" at 925,3200 h40
  text "51" at 3500,3200 h40
  text "52" at 3590,3200 h40
  text "3V3" at 3305,3175 h40
  text "VDD" at 2525,3150 h35
  text "5V" at 460,3130 h40
  text "VDDA" at 3100,3100 h35
  text "5V" at 900,3075 h35
  text "3V3" at 1985,3005 h40 r90
  text "IR" at 2775,3000 h40 r90
  text "1V8" at 1275,2995 h40
  text "IrDA" at 625,2985 h35 r90
  text "RS485" at 710,2985 h35 r90
  text "RS232" at 825,2985 h35 r90
  text "VDD" at 2160,2975 h40 r90
  text "3V3" at 2490,2975 h35 r90
  text "COM" at 3560,2950 h35 r90
  text "VDD" at 2490,2775 h40 r90
  text "Audio" at 2775,2775 h40 r90
  text "VBAT" at 2160,2760 h40 r90
  text "VDD_ADJ" at 1985,2740 h40 r90
  text "USART_RX" at 624.61,2698.92 h35
  text "VDD_ADJ" at 1475,2675 h35
  text "D5V" at 1000,2655 h40 r90
  text "U5V" at 1100,2655 h40 r90
  text "PSU" at 1200,2655 h40 r90
  text "STlk" at 1300,2650 h40 r90
  text "S" at 2520,1240 h35 r90
  text "C" at 2570,1235 h35 r90
  text "PSU" at 290,1015 h35
  text "+" at 25,540 h40 r270
  text "-" at 250,500 h40
  text "GND" at 400,350 h35
  text "2V5" at 1035,350 h35
  text "PC1" at 3827,35 h35
BottomOverlay:
  drawing of 1979 lines, arcs and shapes, not listed
  text "MB1019 rev.C" at 3610,2195 h60
  text "B" at 2520,1510 h35 r90
  text "C" at 2570,1485 h35 r90
Mechanical1:
  lines w5: 4550,475 cw(c5723.78,724.49) 4550,973.99 4550,6800 1505.64,6800 -100,6800 -100,1458.87 -100,0 4550,0 4550,475 ; 4550,475 4550,475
